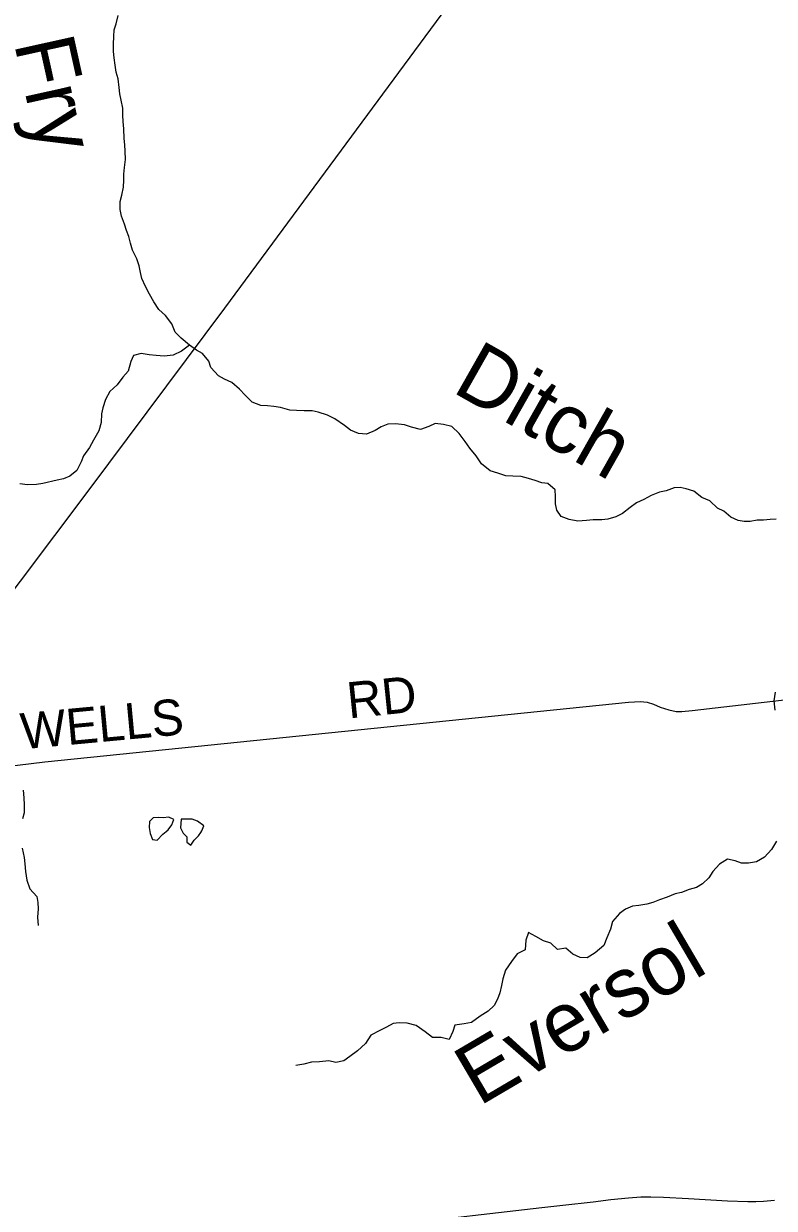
# Model space of a CAD drawing. Extents: x 114843 to 284848, y 317643 to 566895.
# Drawn here: x 145352 to 151603, y 459448 to 469308 of the extents above; entities that cross this region are included whole.
import ezdxf

# ---------------------------------------------------------------- set-up
doc = ezdxf.new("R2010")
doc.units = 0
for name, color, linetype in [('GM_X_County_Road', 7, 'Continuous'), ('GM_X_County_Road_Text', 7, 'Continuous'), ('GM_X_Minor_Lake', 7, 'Continuous'), ('GM_X_Minor_River', 7, 'Continuous'), ('GM_X_Minor_River_Text', 7, 'Continuous'), ('GM_X_US_Route', 7, 'Continuous')]:
    doc.layers.add(name, color=color, linetype=linetype)

msp = doc.modelspace()

# ---------------------------------------------------------------- linework, layer by layer
at = {"layer": 'GM_X_County_Road'}
for points in [[(144815.1, 463998.2), (144842.3, 463909.3), (144999.5, 463315.2), (145032.9, 463240.6), (145072.2, 463190.1), (145126.2, 463160.5), (145204.2, 463134.2), (145299.8, 463137.5), (145527.1, 463163.4), (150387.8, 463659.6), (150489.7, 463665.2), (150543.9, 463660.8), (150597.4, 463643.8), (150651.7, 463620.6), (150724.7, 463596.2), (150785.8, 463584.1), (150833.7, 463583.8), (150917.6, 463591.3), (153533.5, 463893.8)], [(148465.7, 459315.6), (149666.7, 459454.1), (149841.8, 459474.2), (150094.6, 459503.6), (150241.6, 459521.4), (150389.8, 459536.6), (150490.6, 459544.5), (150575.6, 459544.2), (150680.3, 459540.6), (150888, 459529.1), (151214, 459510.2), (151381.5, 459503.8), (151449.1, 459505.6), (151513.3, 459508.4), (151603, 459517.3)]]:
    msp.add_lwpolyline(points, dxfattribs=at)
at = {"layer": 'GM_X_Minor_Lake'}
for points in [[(146538.9, 462584.8), (146554, 462597.4), (146585.9, 462639.6), (146601.7, 462683.8), (146561.5, 462703.6), (146513.4, 462699.3), (146471.3, 462701.1), (146429.3, 462696.9), (146399.4, 462668.7)], [(146826.8, 462575.9), (146836.6, 462590.8), (146852.4, 462633), (146798.1, 462670.7), (146753.9, 462688.5), (146709.9, 462686.3), (146663.8, 462686.1)], [(146399.4, 462668.7), (146397.6, 462616.6), (146403.9, 462566.5), (146424.2, 462516.6), (146464.3, 462512.8), (146510.1, 462561.1), (146538.9, 462584.8)], [(146663.8, 462686.1), (146658.1, 462613.9), (146680.4, 462572), (146710.6, 462540.1), (146710.9, 462496), (146743.1, 462470.1), (146770.9, 462512.3), (146808.8, 462548.6), (146826.8, 462575.9)]]:
    msp.add_lwpolyline(points, dxfattribs=at)
at = {"layer": 'GM_X_Minor_River'}
for points in [[(147254.9, 466157.5), (147196.5, 466215.2), (147148.2, 466267), (147085.8, 466322.7), (147023.5, 466348.4), (146973.3, 466376.2), (146910.8, 466445.9), (146892.5, 466499.9), (146842.1, 466563.7), (146789.8, 466591.4), (146733.5, 466631.1), (146663.1, 466690.8), (146614.7, 466740.6), (146584.3, 466810.5), (146533.9, 466878.3), (146477.5, 466928), (146437.1, 466993.8), (146400.7, 467057.7), (146366.3, 467119.6), (146335.9, 467187.4), (146325.6, 467237.4), (146313.3, 467291.4), (146293, 467349.3), (146258.6, 467423.2), (146242.2, 467481.1), (146227.9, 467535.1), (146207.6, 467587), (146191.3, 467639), (146167, 467704.9), (146154.7, 467760.8), (146156.3, 467828.9), (146170.1, 467881), (146181.8, 467947.1), (146185.5, 468005.1), (146185.2, 468055.1), (146191, 468111.2), (146200.6, 468177.3), (146198.3, 468247.3), (146194, 468299.3), (146189.7, 468353.3), (146185.3, 468431.3), (146179, 468493.3), (146176.7, 468547.3), (146178.4, 468605.4), (146164.1, 468671.3), (146153.8, 468723.3), (146147.5, 468777.3), (146139.1, 468847.3), (146120.8, 468905.2), (146112.5, 468961.2), (146106.2, 469023.2), (146099.9, 469077.2), (146099.6, 469137.2), (146101.3, 469201.2), (146105, 469255.3), (146120.8, 469305.4), (146138.5, 469375.5)], [(146732, 466632.4), (146665.6, 466582.8), (146595.7, 466548.4), (146521.6, 466540), (146455.4, 466545.6), (146397.3, 466551.3), (146331.1, 466563), (146267, 466546.6), (146245.2, 466496.5), (146221.6, 466416.3), (146177.8, 466366), (146130, 466301.7), (146070.2, 466245.4), (146034.5, 466179.2), (146010.8, 466111), (146001, 466060.9), (145997.4, 465988.8), (145977.7, 465918.6), (145934, 465840.3), (145900.3, 465780.1), (145850.5, 465711.8), (145830.7, 465659.7), (145795, 465589.4), (145735.2, 465541.1), (145683.2, 465518.8), (145631.1, 465508.5), (145511, 465479.8), (145459, 465471.6), (145384.8, 465469.2), (145318.7, 465478.8)], [(151618.3, 465182.9), (151568.2, 465180.7), (151512.1, 465176.4), (151460, 465176.1), (151401.9, 465165.8), (151351.9, 465163.5), (151301.7, 465173.3), (151239.5, 465201), (151183.1, 465250.8), (151130.9, 465276.5), (151064.4, 465336.3), (150998.2, 465364), (150933.7, 465417.7), (150869.5, 465437.4), (150819.4, 465447.1), (150769.3, 465444.9), (150701.3, 465420.5), (150647.3, 465408.2), (150577.3, 465381.8), (150517.3, 465347.4), (150455.3, 465319.1), (150403.5, 465280.8), (150339.6, 465230.4), (150283.6, 465204.1), (150217.6, 465183.7), (150167.5, 465177.4), (150093.4, 465177.1), (150039.3, 465172.8), (149965.2, 465168.4), (149895, 465182), (149826.7, 465205.7), (149792.4, 465257.6), (149780.1, 465311.6), (149781.8, 465373.7), (149777.5, 465427.7), (149717.1, 465481.5), (149667, 465485.2), (149610.8, 465505), (149554.6, 465522.7), (149494.4, 465538.4), (149424.2, 465542), (149368.1, 465545.8), (149299.9, 465567.4), (149237.7, 465587.1), (149163.2, 465644.8), (149118.8, 465710.6), (149066.4, 465774.5), (149028, 465830.3), (148977.6, 465898.1), (148917.2, 465953.9), (148848.9, 465971.5), (148778.7, 465981.2), (148726.8, 465954.9), (148656.8, 465930.5), (148582.5, 465950.1), (148524.3, 465967.9), (148448.1, 465977.5), (148384, 465975.1), (148330, 465952.8), (148280.1, 465922.5), (148206.1, 465890.1), (148140, 465897.8), (148073.7, 465923.5), (148023.4, 465963.3), (147943, 466018.9), (147882.7, 466048.6), (147804.4, 466074.2), (147754.3, 466086), (147688.1, 466085.6), (147624, 466089.3), (147567.9, 466091), (147491.6, 466112.6), (147435.4, 466122.4), (147383.3, 466126.1), (147327.2, 466129.8), (147254.9, 466157.5)], [(151609.7, 463742.9), (151598.1, 463670.7), (151606.5, 463594.6)], [(145348, 462927.7), (145352.3, 462865.6), (145356.6, 462807.6), (145355, 462739.5), (145343.2, 462689.3)], [(151620.2, 462504.9), (151578.5, 462434.6), (151520.7, 462370.2), (151454.8, 462331.8), (151386.7, 462321.4), (151330.6, 462321.1), (151276.4, 462340.9), (151212.2, 462354.6), (151146.3, 462312.2), (151090.5, 462251.8), (151056.8, 462197.5), (151004.9, 462149.2), (150955, 462118.9), (150892.9, 462102.5), (150829, 462078.1), (150776.9, 462065.9), (150710.9, 462037.5), (150646.9, 462015.1), (150591, 461994.8), (150540.9, 461980.5), (150474.9, 461968.2), (150422.8, 461963.9), (150362.8, 461937.6), (150312.9, 461901.2), (150255.1, 461836.8), (150239.4, 461772.6), (150207.8, 461698.3)], [(145340.5, 462444.9), (145354.9, 462366.8), (145361.2, 462314.8), (145367.6, 462252.7), (145377.9, 462180.6), (145402.4, 462108.6), (145460.8, 462042.8)], [(145460.8, 462042.8), (145471.1, 461992.8), (145471.4, 461940.7), (145465.7, 461870.5), (145472.1, 461802.4)], [(150207.8, 461698.3), (150182.1, 461636.1), (150112.2, 461575.6), (150044.3, 461533.2), (149986.2, 461536.9), (149926, 461562.7), (149865.6, 461612.5), (149797.5, 461602.1), (149741.1, 461653.9), (149680.9, 461675.6), (149616.6, 461711.4), (149556.3, 461743.1), (149534.6, 461678.9), (149527, 461598.7), (149461.1, 461566.3), (149415.3, 461502), (149363.6, 461431.6), (149341.9, 461357.3), (149332.2, 461303.2), (149316.5, 461241), (149296.7, 461188.8), (149269, 461136.6), (149219.1, 461090.2), (149153.2, 461047.8), (149081.3, 460995.4), (149021.3, 460985), (148941.2, 460972.6), (148925.4, 460920.4), (148895.7, 460852.1), (148829.5, 460869.8), (148755.4, 460869.5), (148695, 460917.3), (148620.6, 460971), (148546.4, 460988.6), (148478.2, 460992.3), (148428.1, 460986), (148374.2, 460955.7), (148318.2, 460929.4), (148242.3, 460888.9), (148198.6, 460820.6), (148132.8, 460758.1), (148066.9, 460711.7), (148017, 460675.3), (147950.9, 460663), (147892.8, 460674.7), (147814.6, 460666.3), (147748.5, 460664), (147684.5, 460647.6), (147618.4, 460637.2)]]:
    msp.add_lwpolyline(points, dxfattribs=at)
at = {"layer": 'GM_X_US_Route'}
msp.add_lwpolyline([(141718.7, 459999.2), (141914.9, 460233), (142056.2, 460415.4), (142314, 460742), (142935.1, 461533.1), (143265.8, 461967.7), (144815.1, 463998.2), (145324.8, 464668.3), (145896.7, 465429.3), (147026.8, 466941), (150809.3, 472065.3)], dxfattribs=at)

# ---------------------------------------------------------------- texts
at = {"layer": 'GM_X_County_Road_Text'}
for s, rotation, p in [('RD', 5.87468, (148059.5, 463524.9)), ('WELLS', 5.34655, (145340.9, 463268.1))]:
    msp.add_text(s, height=300, rotation=rotation, dxfattribs=at).set_placement(p)
at = {"layer": 'GM_X_Minor_River_Text'}
for s, height, rotation, p in [('Fry', 498.92, 282.4577, (145270.7, 469146.2)), ('Ditch', 499.81, 330.47422, (148908.3, 466249)), ('Eversol', 499.85, 30.41739, (149144.1, 460294.2))]:
    msp.add_text(s, height=height, rotation=rotation, dxfattribs=at).set_placement(p)

doc.saveas('drawing.dxf')
